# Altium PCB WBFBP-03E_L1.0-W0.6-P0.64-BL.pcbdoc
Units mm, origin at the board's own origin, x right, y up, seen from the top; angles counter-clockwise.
Board outline 14.06 x 13.54 mm, 2 copper layers (Top Layer, Bottom Layer), stack 0 mm thick; 1 components, 0 nets, 3 pads, 0 vias.
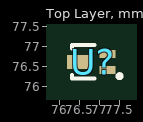
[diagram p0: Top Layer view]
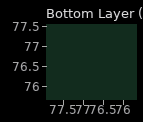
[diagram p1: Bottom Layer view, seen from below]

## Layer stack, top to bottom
Top Layer: signal copper (thickness not stored)
Bottom Layer: signal copper (thickness not stored)

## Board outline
83.913,69.85 69.85,69.85 69.85,83.39 83.913,83.39

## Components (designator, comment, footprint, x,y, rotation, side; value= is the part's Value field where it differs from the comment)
U? "" WBFBP-03E_L1.0-W0.6-P0.64-BL 76.843,76.62 r0 top

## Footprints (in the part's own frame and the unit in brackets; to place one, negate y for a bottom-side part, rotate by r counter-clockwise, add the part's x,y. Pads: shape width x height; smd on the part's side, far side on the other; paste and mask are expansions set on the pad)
WBFBP-03E_L1.0-W0.6-P0.64-BL [mm]
  rect 0.4x0.2 smd: 1(0.368,-0.2) 2(0.368,0.2)
  rect 0.55x0.35 smd: 3(-0.368,0)
  silkscreen extent -0.52,-0.42 0.72,0.42

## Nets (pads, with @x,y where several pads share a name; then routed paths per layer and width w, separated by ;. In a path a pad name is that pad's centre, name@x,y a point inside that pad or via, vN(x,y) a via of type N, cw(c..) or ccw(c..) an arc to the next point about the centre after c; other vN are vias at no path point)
pads on no net: U?.1 U?.2 U?.3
